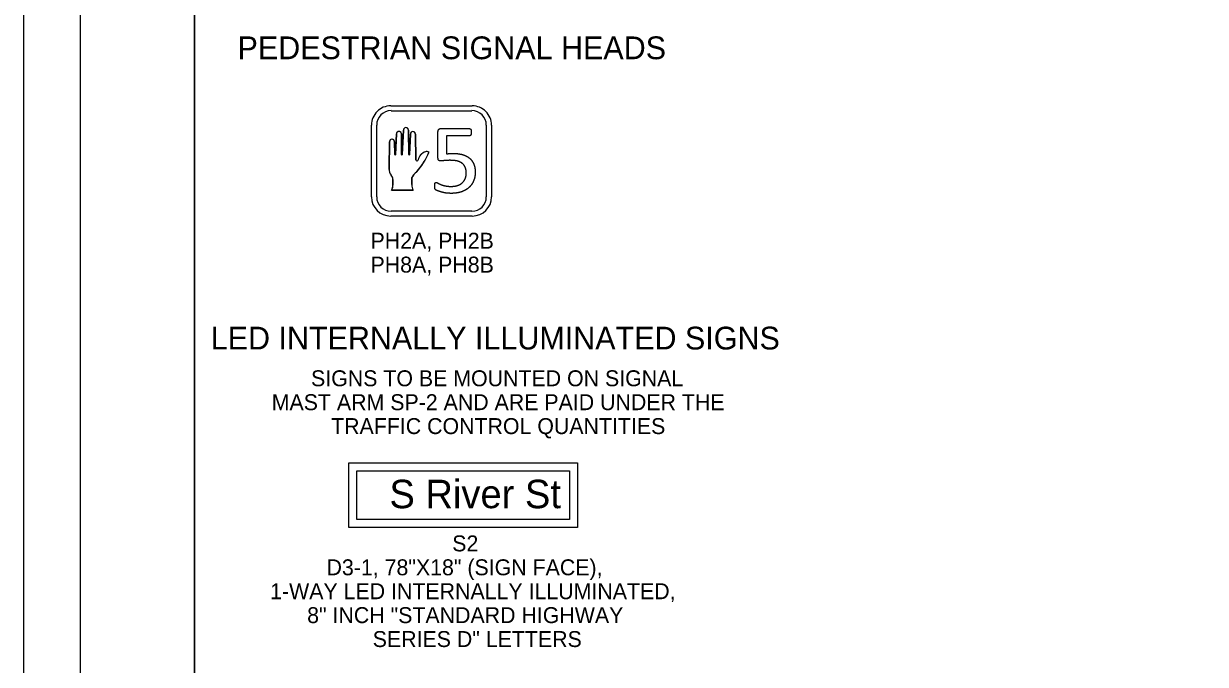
# Model space of a CAD drawing. Extents: x -32.9 to 34, y 0 to 22.3.
# Drawn here: x 0 to 10.37, y 11.39 to 17.02 of the extents above; entities that cross this region are included whole.
import ezdxf

# ---------------------------------------------------------------- set-up
doc = ezdxf.new("R2010")
doc.units = 0
for name, color, linetype in [('Default', 7, 'Continuous'), ('GE_P_Alignment', 7, 'Continuous'), ('GE_P_Driveway_CL', 7, 'Continuous'), ('PF_X_Ground_Line', 7, 'Continuous'), ('PV_P_Curb_Ramp', 7, 'Continuous'), ('PV_P_Saw_Cut_Line', 7, 'Continuous')]:
    doc.layers.add(name, color=color, linetype=linetype)

# ---------------------------------------------------------------- blocks, each defined once
blk = doc.blocks.new('HAND')
at = {"layer": 'Default'}
for points in [[(0.0005, 0.1047), (0.0004, 0.1045), (0.004, 0.1776), (0.004, 0.1776)], [(0.0186, 0.1776), (0.0186, 0.1776), (0.0199, 0.105), (0.0199, 0.105)], [(-0.0387, 0.0626), (-0.0387, 0.0626), (-0.0372, 0.143), (-0.0372, 0.143)], [(-0.0227, 0.143), (-0.0227, 0.143), (-0.0215, 0.105), (-0.0215, 0.105)], [(-0.0196, 0.1047), (-0.0197, 0.1045), (-0.0167, 0.1665), (-0.0167, 0.1665)], [(-0.0022, 0.1665), (-0.0022, 0.1665), (-0.0014, 0.105), (-0.0014, 0.105)], [(0.0218, 0.1047), (0.0218, 0.1045), (0.0247, 0.1659), (0.0247, 0.1659)], [(0.0392, 0.1659), (0.0392, 0.1659), (0.0402, 0.0888), (0.0402, 0.0888)], [(0.0477, 0.089), (0.0477, 0.089)], [(-0.032, 0.0432), (-0.032, 0.0432)], [(0.0284, 0.0364), (0.0284, 0.0364), (0.0284, 0.0154), (0.0284, 0.0154)], [(-0.0271, 0.0154), (-0.0271, 0.0154), (-0.0271, 0.0308), (-0.0271, 0.0308)], [(0.0327, -0.0008), (-0.0313, -0.0008), (-0.0313, -0.0008)], [(0.0327, -0.0008), (0.0327, -0.0008)]]:
    blk.add_lwpolyline(points, dxfattribs=at)
for centre, radius, start, end in [((0.0113, 0.1776), 0.00726, 0, 180), ((-0.03, 0.143), 0.00726, 0, 180), ((-0.0094, 0.1665), 0.00726, 0, 180), ((0.032, 0.1659), 0.00726, 0, 180), ((-0.0206, 0.1048), 0.000943, 167.1401, 358.6099), ((-0.0005, 0.1048), 0.000943, 167.1401, 358.6099), ((0.0208, 0.1048), 0.000943, 167.1401, 358.6099), ((-0.1141, 0.1925), 0.2098, 318.2058, 337.3712), ((0.078, 0.0836), 0.0308, 107.2466, 169.8826), ((0.073, 0.1019), 0.0119, 56.229, 110.2726), ((0.0439, 0.0907), 0.00414, 208.0703, 335.996), ((-0.011, 0.0613), 0.0278, 177.3964, 220.6574), ((-0.0476, 0.0298), 0.0205, 2.7749, 40.7212), ((0.0742, 0.0112), 0.0523, 127.5194, 151.0809), ((-0.0593, 0.0151), 0.0322, 330.2887, 0.5181), ((0.0606, 0.0151), 0.0322, 179.4819, 209.7113)]:
    blk.add_arc(centre, radius, start, end, dxfattribs=at)

msp = doc.modelspace()

# ---------------------------------------------------------------- linework, layer by layer
at = {"layer": 'GE_P_Alignment'}
msp.add_lwpolyline([(0, 0), (34, 0), (34, 22), (0, 22)], close=True, dxfattribs=at)
at = {"layer": 'GE_P_Driveway_CL'}
for p, q in [((3.221, 16.298), (3.937, 16.298)), ((3.225, 16.256), (3.933, 16.256)), ((3.052, 15.499), (3.052, 16.13)), ((3.098, 15.499), (3.098, 16.13)), ((3.662, 16.099), (3.912, 16.099)), ((4.06, 16.13), (4.06, 15.499)), ((4.106, 16.13), (4.106, 15.499)), ((3.636, 15.842), (3.636, 16.071)), ((3.963, 15.718), (3.963, 15.718)), ((3.933, 15.373), (3.225, 15.373)), ((3.937, 15.331), (3.221, 15.331))]:
    msp.add_line(p, q, dxfattribs=at)
for points in [[(3.333, 16.086), (3.323, 15.871), (3.323, 15.871)], [(3.381, 15.871), (3.377, 16.086)], [(3.211, 15.984), (3.207, 15.746)], [(3.258, 15.871), (3.254, 15.984), (3.254, 15.984)], [(3.272, 16.053), (3.263, 15.871), (3.263, 15.871)], [(3.317, 15.871), (3.315, 16.053), (3.315, 16.053)], [(3.395, 16.051), (3.386, 15.871), (3.386, 15.871)], [(3.441, 15.824), (3.438, 16.051)], [(3.912, 16.034), (3.711, 16.034), (3.711, 15.877)], [(3.263, 15.87), (3.263, 15.87), (3.263, 15.87)], [(3.323, 15.87), (3.323, 15.87), (3.323, 15.87)], [(3.386, 15.87), (3.386, 15.87), (3.386, 15.87)], [(3.463, 15.824), (3.463, 15.824)], [(3.226, 15.689), (3.226, 15.689)], [(3.406, 15.607), (3.406, 15.669)], [(3.229, 15.559), (3.418, 15.559)], [(3.241, 15.653), (3.241, 15.607)]]:
    msp.add_lwpolyline(points, dxfattribs=at)
for centre, major_axis, start_param, end_param in [((3.221, 16.13), (0.169, 0), 1.570796, 3.141593), ((3.937, 16.13), (0.169, 0), 6.283185, 7.853982), ((3.225, 16.13), (0.127, 0), 1.570796, 3.141593), ((3.933, 16.13), (0.127, 0), 6.283185, 7.853982), ((3.293, 16.053), (0.0215, 0), 0, 3.141593), ((3.355, 16.086), (0.0215, 0), 6.283185, 9.424778), ((3.233, 15.984), (0.0215, 0), 0, 3.141593), ((3.416, 16.051), (0.0215, 0), 0, 3.141593), ((3.26, 15.871), (0.0028, 0), 2.917145, 6.054008), ((3.26, 15.871), (0.0028, 0), 6.061637, 6.258923), ((3.32, 15.871), (0.0028, 0), 2.917145, 6.049226), ((3.32, 15.871), (0.0028, 0), 6.126272, 6.258923), ((3.383, 15.871), (0.0028, 0), 2.917145, 6.058743), ((3.383, 15.871), (0.0028, 0), 6.099269, 6.258923), ((2.983, 16.13), (0.623, 0), 5.553739, 5.888238), ((3.553, 15.808), (0.0914, 0), 1.871807, 2.965011), ((3.538, 15.862), (0.0353, 0), 0.981382, 1.92462), ((3.452, 15.829), (0.0123, 0), 3.631512, 5.864236), ((3.289, 15.743), (0.0825, 0), 3.096152, 3.851198), ((3.18, 15.65), (0.0609, 0), 0.048431, 0.710719), ((3.542, 15.594), (0.155, 0), 2.225634, 2.636859), ((3.146, 15.606), (0.0956, 0), 5.764626, 6.292228), ((3.501, 15.606), (0.0956, 0), 3.13255, 3.660152), ((3.221, 15.499), (0.169, 0), 3.141593, 4.712389), ((3.225, 15.499), (0.127, 0), 3.141593, 4.712389), ((3.933, 15.499), (0.127, 0), 4.712389, 6.283185), ((3.937, 15.499), (0.169, 0), 4.712389, 6.283185)]:
    msp.add_ellipse(centre, major_axis=major_axis, ratio=0.995332, start_param=start_param, end_param=end_param, dxfattribs=at)
for points in [[(3.636, 16.071), (3.636, 16.085), (3.643, 16.092)], [(3.643, 16.092), (3.65, 16.099), (3.662, 16.099)], [(3.912, 16.099), (3.915, 16.099), (3.918, 16.097)], [(3.918, 16.097), (3.922, 16.095), (3.924, 16.091)], [(3.924, 16.091), (3.926, 16.087), (3.927, 16.081)], [(3.927, 16.081), (3.928, 16.075), (3.928, 16.067)], [(3.924, 16.043), (3.92, 16.034), (3.912, 16.034)], [(3.928, 16.067), (3.928, 16.051), (3.924, 16.043)], [(3.711, 15.877), (3.726, 15.879), (3.741, 15.879)], [(3.741, 15.879), (3.756, 15.88), (3.777, 15.88)], [(3.777, 15.88), (3.823, 15.88), (3.858, 15.868)], [(3.858, 15.868), (3.893, 15.857), (3.916, 15.836)], [(3.641, 15.821), (3.636, 15.826), (3.636, 15.842)], [(3.659, 15.815), (3.647, 15.815), (3.641, 15.821)], [(3.694, 15.818), (3.675, 15.815), (3.659, 15.815)], [(3.74, 15.82), (3.714, 15.82), (3.694, 15.818)], [(3.805, 15.814), (3.778, 15.82), (3.74, 15.82)], [(3.849, 15.793), (3.832, 15.807), (3.805, 15.814)], [(3.875, 15.759), (3.867, 15.779), (3.849, 15.793)], [(3.916, 15.836), (3.939, 15.815), (3.951, 15.785)], [(3.951, 15.785), (3.963, 15.755), (3.963, 15.718)], [(3.874, 15.657), (3.884, 15.679), (3.884, 15.711)], [(3.884, 15.711), (3.884, 15.738), (3.875, 15.759)], [(3.963, 15.718), (3.963, 15.673), (3.948, 15.638)], [(3.607, 15.596), (3.607, 15.603), (3.608, 15.609)], [(3.608, 15.583), (3.607, 15.588), (3.607, 15.596)], [(3.608, 15.609), (3.609, 15.615), (3.61, 15.619)], [(3.609, 15.573), (3.608, 15.577), (3.608, 15.583)], [(3.612, 15.567), (3.61, 15.57), (3.609, 15.573)], [(3.61, 15.619), (3.612, 15.623), (3.615, 15.624)], [(3.616, 15.561), (3.613, 15.564), (3.612, 15.567)], [(3.615, 15.624), (3.617, 15.626), (3.62, 15.626)], [(3.631, 15.553), (3.62, 15.558), (3.616, 15.561)], [(3.62, 15.626), (3.624, 15.626), (3.634, 15.621)], [(3.634, 15.621), (3.643, 15.615), (3.658, 15.609)], [(3.658, 15.609), (3.674, 15.602), (3.696, 15.597)], [(3.696, 15.597), (3.719, 15.591), (3.751, 15.591)], [(3.751, 15.591), (3.78, 15.591), (3.804, 15.598)], [(3.804, 15.598), (3.829, 15.605), (3.846, 15.62)], [(3.905, 15.579), (3.877, 15.555), (3.838, 15.542)], [(3.846, 15.62), (3.864, 15.635), (3.874, 15.657)], [(3.948, 15.638), (3.933, 15.603), (3.905, 15.579)], [(3.661, 15.543), (3.643, 15.548), (3.631, 15.553)], [(3.703, 15.533), (3.68, 15.537), (3.661, 15.543)], [(3.753, 15.53), (3.727, 15.53), (3.703, 15.533)], [(3.838, 15.542), (3.8, 15.53), (3.753, 15.53)]]:
    msp.add_open_spline(points, degree=2, dxfattribs=at)
at = {"layer": 'PV_P_Curb_Ramp'}
for points in [[(0.5, 21.5), (1.5, 21.5), (1.5, 0.5), (0.5, 0.5)], [(1.5, 21.5), (33.5, 21.5), (33.5, 0.5), (1.5, 0.5)]]:
    msp.add_lwpolyline(points, close=True, dxfattribs=at)
at = {"layer": 'PV_P_Saw_Cut_Line'}
for points in [[(2.855, 13.163), (4.861, 13.163), (4.861, 12.597), (2.855, 12.597)], [(2.925, 13.093), (4.791, 13.093), (4.791, 12.667), (2.925, 12.667)]]:
    msp.add_lwpolyline(points, close=True, dxfattribs=at)

# ---------------------------------------------------------------- block references
at = {"layer": 'GE_P_Driveway_CL', "xscale": 2.9676009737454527, "yscale": 2.953749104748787, "rotation": -4.08392135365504e-09}
msp.add_blockref('HAND', (3.321, 15.561), dxfattribs=at)

# ---------------------------------------------------------------- texts
at = {"layer": 'PF_X_Ground_Line'}
for s, height, p in [('PEDESTRIAN SIGNAL HEADS', 0.2, (1.877, 16.708)), ('PH2A, PH2B', 0.14, (3.044, 15.044)), ('PH8A, PH8B', 0.14, (3.044, 14.834)), ('LED INTERNALLY ILLUMINATED SIGNS', 0.2, (1.642, 14.159))]:
    msp.add_text(s, height=height, dxfattribs=at).set_placement(p)
at = {"layer": 'PV_P_Saw_Cut_Line'}
for s, height, p in [('SIGNS TO BE MOUNTED ON SIGNAL ', 0.14, (2.522, 13.836)), ('MAST ARM SP-2 AND ARE PAID UNDER THE ', 0.14, (2.177, 13.626)), ('TRAFFIC CONTROL QUANTITIES', 0.14, (2.698, 13.416)), ('S River St', 0.25, (3.21, 12.765)), ('S2', 0.14, (3.761, 12.386)), ('D3-1, 78"X18" (SIGN FACE),', 0.14, (2.658, 12.176)), ('1-WAY LED INTERNALLY ILLUMINATED, ', 0.14, (2.163, 11.966)), ('8" INCH "STANDARD HIGHWAY', 0.14, (2.488, 11.756)), (' SERIES D" LETTERS', 0.14, (3.011, 11.546))]:
    msp.add_text(s, height=height, dxfattribs=at).set_placement(p)

doc.saveas('drawing.dxf')
